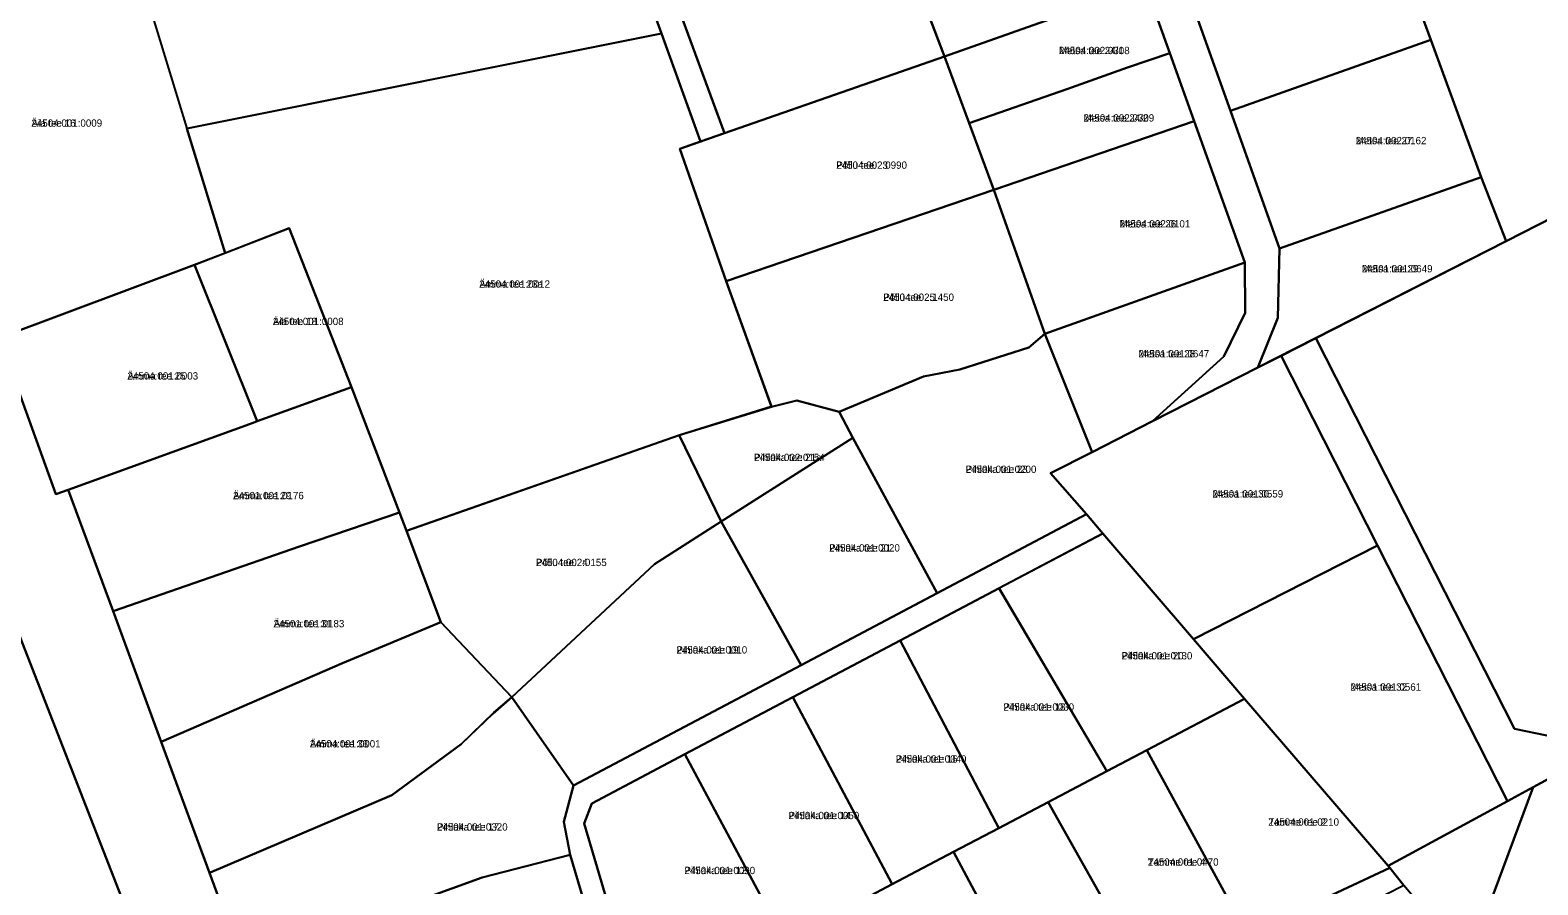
# Model space of a CAD drawing. Extents: x 551291 to 575799, y 6581704 to 6610137.
# Drawn here: x 551707.6 to 552016.8, y 6591239.3 to 6591414.5 of the extents above; entities that cross this region are included whole.
import ezdxf

# ---------------------------------------------------------------- set-up
doc = ezdxf.new("R2010")
doc.units = 0
for name, color, linetype in [('L_AADRESS', 7, 'Continuous'), ('PIIR', 7, 'Continuous'), ('TUNNUS', 7, 'Continuous')]:
    doc.layers.add(name, color=color, linetype=linetype)

msp = doc.modelspace()

# ---------------------------------------------------------------- linework, layer by layer
at = {"layer": 'PIIR'}
for points in [[(551963.03, 6591496.81), (551966.6, 6591498.2), (551982.29, 6591504.34), (552012.15, 6591506.17), (552048.62, 6591508.34), (552068.24, 6591400.79), (552039.52, 6591386.16), (552010.35, 6591371.3), (552005.22, 6591384.4), (551994.88, 6591412.56), (551984.51, 6591440.81), (551973.77, 6591468.81)], [(551739.8, 6591394.36), (551725.5, 6591441.16), (551764.44, 6591452), (551806.26, 6591461.72), (551814.99, 6591461.19), (551822.3, 6591454.36), (551837.11, 6591413.85)], [(551725.48, 6591441.18), (551739.78, 6591394.37), (551747.59, 6591368.85), (551741.3, 6591366.42), (551701.29, 6591351.43), (551680.23, 6591405.99), (551675.09, 6591404.12), (551668.18, 6591422.91)], [(551984.51, 6591440.81), (551994.88, 6591412.56), (551953.76, 6591398.01), (551943.72, 6591426.15)], [(551884.51, 6591437.08), (551895.12, 6591409.14), (551849.99, 6591393.39), (551839.68, 6591421.48)], [(551889, 6591425.25), (551911.93, 6591430.09), (551924.48, 6591434.48), (551931.64, 6591436.98), (551936.36, 6591423.79), (551895.12, 6591409.14)], [(551895.12, 6591409.14), (551936.36, 6591423.79), (551941.34, 6591409.83), (551932.68, 6591406.91), (551920.23, 6591402.45), (551900.17, 6591395.46)], [(551837.1, 6591413.86), (551845.11, 6591391.69), (551840.85, 6591390.2), (551850.39, 6591363.11), (551859.67, 6591337.38), (551840.76, 6591331.53), (551784.81, 6591311.87), (551783.37, 6591315.63), (551773.51, 6591341.35), (551760.73, 6591373.93), (551747.59, 6591368.85), (551739.78, 6591394.37)], [(551953.76, 6591398.01), (551994.88, 6591412.56), (552005.22, 6591384.4), (551963.81, 6591369.75)], [(551895.12, 6591409.14), (551905.22, 6591381.78), (551850.39, 6591363.1), (551840.83, 6591390.19), (551849.99, 6591393.39)], [(551900.17, 6591395.46), (551920.23, 6591402.45), (551932.68, 6591406.91), (551941.34, 6591409.83), (551946.33, 6591395.88), (551905.22, 6591381.78)], [(551956.72, 6591366.88), (551915.69, 6591352.31), (551905.22, 6591381.78), (551946.33, 6591395.88)], [(552010.35, 6591371.31), (551959.38, 6591345.37), (551963.51, 6591355.58), (551963.81, 6591369.75), (552005.22, 6591384.4)], [(552012.05, 6591271.31), (551971.28, 6591351.4), (552010.35, 6591371.3), (552039.52, 6591386.16), (552065.96, 6591295.57), (552018.66, 6591269.96)], [(551864.86, 6591338.61), (551859.68, 6591337.35), (551850.39, 6591363.1), (551905.22, 6591381.78), (551915.69, 6591352.31), (551912.42, 6591349.51), (551898.28, 6591344.94), (551890.81, 6591343.53), (551873.52, 6591336.31)], [(551760.73, 6591373.93), (551773.51, 6591341.35), (551754.21, 6591334.36), (551741.3, 6591366.42)], [(551741.3, 6591366.42), (551754.21, 6591334.36), (551753.39, 6591334.02), (551715.45, 6591320.33), (551712.87, 6591319.4), (551701.29, 6591351.43)], [(551915.69, 6591352.31), (551956.72, 6591366.88), (551956.77, 6591356.57), (551952.4, 6591347.64), (551937.82, 6591334.37), (551925.43, 6591328.05)], [(551916.89, 6591323.75), (551924.24, 6591315.29), (551893.63, 6591299.12), (551876.34, 6591330.98), (551873.52, 6591336.31), (551890.81, 6591343.53), (551898.28, 6591344.94), (551912.42, 6591349.51), (551915.69, 6591352.31), (551925.43, 6591328.05)], [(551983.94, 6591308.89), (551964.15, 6591347.77), (551971.28, 6591351.4), (552012.05, 6591271.31), (552018.66, 6591269.96), (552065.96, 6591295.57), (552092.91, 6591310.17), (552095.07, 6591302.23), (552093.99, 6591301.64), (552088.53, 6591298.69), (552015.83, 6591259.33), (552010.61, 6591256.5)], [(551924.24, 6591315.29), (551916.89, 6591323.75), (551925.43, 6591328.05), (551937.82, 6591334.37), (551959.42, 6591345.37), (551964.15, 6591347.77), (551983.94, 6591308.89), (551946.17, 6591289.68), (551927.6, 6591311.36)], [(551754.21, 6591334.36), (551773.51, 6591341.35), (551783.37, 6591315.63), (551762.83, 6591308.66), (551724.64, 6591295.4), (551715.45, 6591320.33), (551753.39, 6591334.02)], [(551840.75, 6591331.52), (551859.68, 6591337.35), (551864.86, 6591338.61), (551873.52, 6591336.31), (551876.34, 6591330.98), (551849.32, 6591313.78)], [(551592.26, 6591318.17), (551621.99, 6591332.29), (551623.99, 6591329.04), (551632.52, 6591311.28), (551638.82, 6591301.29), (551648.47, 6591293.24), (551660.58, 6591291.58), (551671.63, 6591296.03), (551697.08, 6591311.6), (551731.03, 6591224.85), (551725.67, 6591222.15), (551699.31, 6591208.85), (551670.73, 6591194.44), (551633.68, 6591175.75), (551582.09, 6591146.82), (551586.14, 6591107.57), (551562.34, 6591100.09), (551552.1, 6591119.71), (551549.82, 6591157.52), (551565.91, 6591305.65), (551578.48, 6591311.61)], [(551784.81, 6591311.87), (551840.75, 6591331.52), (551849.32, 6591313.78), (551835.65, 6591305.08), (551806.37, 6591277.83), (551791.81, 6591293.2)], [(551849.32, 6591313.78), (551876.34, 6591330.98), (551893.63, 6591299.12), (551865.72, 6591284.37)], [(551762.83, 6591308.66), (551783.37, 6591315.63), (551784.81, 6591311.87), (551791.81, 6591293.2), (551771.71, 6591284.76), (551734.51, 6591268.62), (551724.64, 6591295.4)], [(551835.65, 6591305.08), (551849.32, 6591313.78), (551865.72, 6591284.37), (551819.04, 6591259.7), (551806.37, 6591277.83)], [(551906.29, 6591300.12), (551927.6, 6591311.36), (551946.17, 6591289.68), (551956.64, 6591277.45), (551936.63, 6591266.94), (551928.4, 6591262.61)], [(551956.64, 6591277.45), (551946.17, 6591289.68), (551983.94, 6591308.89), (552010.61, 6591256.5), (551986.13, 6591243.2)], [(551906.33, 6591300.12), (551928.43, 6591262.61), (551916.4, 6591256.28), (551906.25, 6591250.94), (551886.01, 6591289.4)], [(552005.77, 6591232.17), (552015.83, 6591259.33), (552088.53, 6591298.69), (552112.37, 6591206.21), (552049.91, 6591174.23), (552042.31, 6591189.1)], [(551806.37, 6591277.83), (551802.5, 6591274.41), (551796, 6591268.19), (551781.76, 6591257.73), (551744.41, 6591241.79), (551734.51, 6591268.62), (551771.71, 6591284.76), (551791.81, 6591293.2)], [(551864.01, 6591277.78), (551886.01, 6591289.4), (551906.25, 6591250.94), (551896.98, 6591246.06), (551884.41, 6591239.44)], [(551744.41, 6591241.79), (551781.76, 6591257.73), (551796, 6591268.19), (551802.72, 6591274.63), (551806.37, 6591277.83), (551819.04, 6591259.7), (551817.04, 6591252.23), (551818.36, 6591245.46), (551800.32, 6591240.84), (551751.32, 6591223.06)], [(551841.89, 6591266.09), (551864.01, 6591277.78), (551884.41, 6591239.44), (551874.65, 6591234.3), (551862.38, 6591227.84)], [(551936.63, 6591266.94), (551956.64, 6591277.45), (551986.13, 6591243.2), (551986.45, 6591242.8), (551957.26, 6591229.16)], [(551821.21, 6591251.88), (551822.78, 6591256), (551841.89, 6591266.09), (551862.38, 6591227.84), (551853.31, 6591223.07), (551832.93, 6591212.34)], [(551928.43, 6591262.61), (551936.66, 6591266.94), (551957.29, 6591229.16), (551937.5, 6591218.74), (551916.4, 6591256.28)], [(551986.45, 6591242.8), (551986.13, 6591243.2), (552010.61, 6591256.5), (552015.83, 6591259.33), (552005.77, 6591232.17), (552042.31, 6591189.1), (552049.91, 6591174.23), (552072.65, 6591129.71), (552065.53, 6591126.08), (552063.05, 6591130.94), (552061.12, 6591134.72), (552035.62, 6591184.65), (552022.81, 6591199.75), (551989.34, 6591239.21)], [(551906.25, 6591250.94), (551916.4, 6591256.28), (551937.5, 6591218.74), (551917.26, 6591208.12), (551896.98, 6591246.06)], [(551800.32, 6591240.84), (551818.36, 6591245.46), (551823.84, 6591227.04), (551762.65, 6591205.81), (551758.13, 6591204.61), (551751.32, 6591223.06)], [(551874.65, 6591234.3), (551884.41, 6591239.44), (551896.98, 6591246.06), (551917.26, 6591208.12), (551895.69, 6591195.68)], [(551986.45, 6591242.8), (551989.34, 6591239.21), (551970.94, 6591229.81), (551950.07, 6591219.1), (551928.94, 6591208.12), (551906.07, 6591196.24), (551887.24, 6591186.46), (551866.46, 6591175.69), (551850.49, 6591167.41), (551847.77, 6591162.31), (551844.57, 6591173.08), (551848.73, 6591172.06), (551873.13, 6591184.9), (551895.69, 6591195.68), (551917.26, 6591208.12), (551937.5, 6591218.74), (551957.29, 6591229.16)]]:
    msp.add_lwpolyline(points, close=True, dxfattribs=at)
for points in [[(551839.68, 6591421.48), (551849.99, 6591393.39), (551845.11, 6591391.69), (551837.1, 6591413.86), (551822.3, 6591454.36)], [(551943.72, 6591426.15), (551953.76, 6591398.01), (551963.81, 6591369.75), (551963.51, 6591355.58), (551959.42, 6591345.37), (551937.82, 6591334.37), (551952.4, 6591347.64), (551956.77, 6591356.57), (551956.72, 6591366.88), (551946.33, 6591395.88), (551941.34, 6591409.83), (551936.36, 6591423.79)], [(551701.29, 6591351.43), (551712.87, 6591319.4), (551715.45, 6591320.33), (551724.64, 6591295.4), (551734.51, 6591268.62), (551744.41, 6591241.79), (551751.32, 6591223.06), (551758.13, 6591204.61), (551765.54, 6591184.52), (551772.34, 6591166.09), (551782.64, 6591144.59), (551792.69, 6591117.63), (551801.16, 6591094.92), (551808.64, 6591074.74), (551819.62, 6591045.45), (551809.29, 6591041.41), (551800.02, 6591037.82), (551756.11, 6591156.6), (551743.63, 6591190.71), (551732.76, 6591220.16), (551731.03, 6591224.85), (551697.08, 6591311.6)], [(551823.84, 6591227.04), (551818.36, 6591245.46), (551817.04, 6591252.23), (551819.04, 6591259.7), (551865.72, 6591284.37), (551893.63, 6591299.12), (551924.24, 6591315.29), (551927.6, 6591311.36), (551906.33, 6591300.12), (551886.01, 6591289.4), (551864.01, 6591277.78), (551841.89, 6591266.09), (551822.78, 6591256), (551821.21, 6591251.88), (551832.93, 6591212.34)]]:
    msp.add_lwpolyline(points, dxfattribs=at)

# ---------------------------------------------------------------- texts
at = {"layer": 'L_AADRESS'}
for s, p in [('Metsa tee 24/1', (551918.61, 6591409.62)), ('Äia tee 16', (551707.89, 6591394.74)), ('Metsa tee 24/2', (551923.64, 6591395.8)), ('Metsa tee 27', (551979.47, 6591391.15)), ('Põllu tee 23', (551872.94, 6591386.12)), ('Metsa tee 26', (551931.04, 6591374.09)), ('Metsa tee 29', (551980.72, 6591364.88)), ('Ämma tee 23a', (551799.73, 6591361.74)), ('Põllu tee 25', (551882.58, 6591359.04)), ('Äia tee 18', (551757.4, 6591354.08)), ('Metsa tee 28', (551934.92, 6591347.46)), ('Ämma tee 25', (551727.57, 6591342.91)), ('Pihlaka tee 21a', (551856.07, 6591326.2)), ('Pihlaka tee 23', (551899.48, 6591323.77)), ('Ämma tee 29', (551749.24, 6591318.38)), ('Metsa tee 30', (551950.09, 6591318.73)), ('Pihlaka tee 21', (551871.48, 6591307.65)), ('Põllu tee 24', (551811.36, 6591304.67)), ('Ämma tee 31', (551757.55, 6591292.12)), ('Pihlaka tee 19', (551840.17, 6591286.74)), ('Pihlaka tee 20', (551931.46, 6591285.54)), ('Metsa tee 32', (551978.39, 6591279.13)), ('Pihlaka tee 18', (551907.22, 6591275.03)), ('Ämma tee 33', (551764.99, 6591267.49)), ('Pihlaka tee 16', (551885.13, 6591264.38)), ('Pihlaka tee 14', (551863.15, 6591252.79)), ('Pihlaka tee 17', (551791.04, 6591250.44)), ('Tamme tee 2', (551961.54, 6591251.46)), ('Tamme tee 4', (551936.84, 6591243.25)), ('Pihlaka tee 12', (551841.8, 6591241.52))]:
    msp.add_text(s, height=1.5, dxfattribs=at).set_placement(p)
at = {"layer": 'TUNNUS'}
for s, p in [('24504:002:0308', (551918.61, 6591409.62)), ('24504:001:0009', (551707.89, 6591394.74)), ('24504:002:0309', (551923.64, 6591395.8)), ('24504:002:0162', (551979.47, 6591391.15)), ('24504:002:0990', (551872.94, 6591386.12)), ('24504:002:0101', (551931.04, 6591374.09)), ('24501:001:0649', (551980.72, 6591364.88)), ('24504:001:0012', (551799.73, 6591361.74)), ('24504:002:1450', (551882.58, 6591359.04)), ('24504:001:0008', (551757.4, 6591354.08)), ('24501:001:0647', (551934.92, 6591347.46)), ('24504:001:0003', (551727.57, 6591342.91)), ('24504:002:0154', (551856.07, 6591326.2)), ('24504:001:0200', (551899.48, 6591323.77)), ('24501:001:0176', (551749.24, 6591318.38)), ('24501:001:0559', (551950.09, 6591318.73)), ('24504:001:0020', (551871.48, 6591307.65)), ('24504:002:0155', (551811.36, 6591304.67)), ('24501:001:0183', (551757.55, 6591292.12)), ('24504:001:0010', (551840.17, 6591286.74)), ('24504:001:0130', (551931.46, 6591285.54)), ('24501:001:0561', (551978.39, 6591279.13)), ('24504:001:0030', (551907.22, 6591275.03)), ('24504:001:0001', (551764.99, 6591267.49)), ('24504:001:0040', (551885.13, 6591264.38)), ('24504:001:0050', (551863.15, 6591252.79)), ('24504:001:0320', (551791.04, 6591250.44)), ('24504:001:0210', (551961.54, 6591251.46)), ('24504:001:0470', (551936.84, 6591243.25)), ('24504:001:0090', (551841.8, 6591241.52))]:
    msp.add_text(s, height=1.5, dxfattribs=at).set_placement(p)

doc.saveas('drawing.dxf')
